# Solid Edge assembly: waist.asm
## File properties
Author: nakano
Template: iso metric assembly.asm
Last saved by: nakano
Revision: 28
Application: Solid Edge
Username: nakano
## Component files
Top-Mount BR-KT.par
asb-204.par
hitec hs-805bb.par
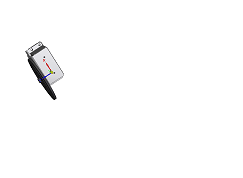
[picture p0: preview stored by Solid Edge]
